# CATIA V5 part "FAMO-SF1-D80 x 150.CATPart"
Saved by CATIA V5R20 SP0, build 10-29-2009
Part number: FAMO-SF1-D80 x 150
Definition: NONE
Nomenclature: FAMO-SF1-D80 x 150
Source: Unknown
Description: FAMO-SF1-D80 x 150
Bounding box of the stored display mesh (mm): x -73 to 77, y -55.5 to 55.5, z -55.5 to 55.5
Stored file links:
  C:\Users\Utente\Desktop\IO LAVORO\3D X SITO CF\X SITO\FAMO\FAMO-SF1-D80 x 150.CATPart
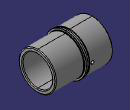
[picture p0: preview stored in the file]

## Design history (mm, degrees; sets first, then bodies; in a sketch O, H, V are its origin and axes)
Body1 "FAMO-SF1-D80 x 150" (main body)
  Solid1: solid without history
